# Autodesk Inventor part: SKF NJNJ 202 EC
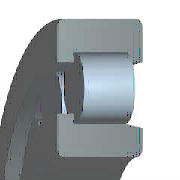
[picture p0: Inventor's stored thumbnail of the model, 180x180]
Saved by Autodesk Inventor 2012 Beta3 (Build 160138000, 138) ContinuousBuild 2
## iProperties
IsCustomPart: 0
Created: 2010-11
Part Number: SKF NJNJ 202 EC
Material: Steel, Mild
Description: Cylindrical Roller Bearings Single Row type NJ SKF
Document SubType Name: Modeling
Standard: SKF NJ
Designer: Beta-8540w
Language: en-US
Size Designation: SKF NJNJ 202 EC
Categories: <MemberInstance><Categories><Category DisplayName="Shaft Parts" InternalName="7f7aeb1f-a693-4053-b835-cee3144e0d98" Mnemonic="SHFT"><Category DisplayName="Beari
Density: 7.86 g/cm^3
Author: Beta-8540w
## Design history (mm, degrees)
node "WorkPlane1"
workplane "Work Plane2"
node "WorkPlane2"
node "Sketch1"
node "WorkPoint1"
node "Sketch3"
node "WorkPoint2"
node "WorkAxis1"
sketch "Sketch4"
  geometry: C1 r 17.5 at (0, 0) reference
hole "Hole1" sketch "Sketch4" diameter "d6" = 15 (= Diam); stored, may be unused: countersink angle "d10" = 60 deg, drill point angle "d12" = 118 deg; dims "d7" = 6, "d8" = 4, "d9" = 2, "d11" = 8
pattern_circular "PolarArray1" dims angle "d31" = 360 deg
fillet "Fillet1" dims "d32" = 0.6 (= r)
body "Solid1"
extrude "Extrusion1" new body distance "d3" = 11 (= B); taper "d4" = 0 deg
revolve "Revolution1" stored, may be unused: angle "d25" = 360 deg
revolve "Revolution2" stored, may be unused: angle "d28" = 360 deg
node "Sketch2" dims "d2" = 35 (= DD)
sketch "Sketch5"
  geometry: L1 (13.95, 1.925)-(15.15, 1.925); L2 (13.95, 0)-(13.95, 1.925); L3 (10.95, 0)-(13.95, 0); L4 (10.95, 1.925)-(10.95, 0); L5 (9.65, 1.925)-(10.95, 1.925); L6 (9.65, 9.075)-(9.65, 1.925); L7 (9.311, 11)-(9.65, 9.075); L8 (13.95, 11)-(9.311, 11); L9 (13.95, 9.075)-(13.95, 11); L10 (15.15, 9.075)-(13.95, 9.075); L11 (15.15, 1.925)-(15.15, 9.075); L12 (-17.5, 0)-(17.5, 0) reference; L13 (-17.5, 11)-(17.5, 11) reference; L14 (0, 34.914)-(0, -22.914); L15 (0, -34.479)-(0, 46.479) reference
  constraints: 24 end point, 5 collinear, 5 horizontal, 5 vertical, 1 point on line
  dimensions: "d16" = 7.15 distance of L1.end L10.start (= msp_l0); "d18" = 1.925 distance of L2.start L1.start (= 0.5 x B - 0.5 x msp_l0); "d24" = 80 deg angle of L7 L8; "d33" = 5.5 distance between parallel lines of L11 L6 (= msp_dd0); "d34" = 27.9 diameter of L9 L14 (= DD1); "d35" = 30.3 diameter of L11 L14 (= EE); "d36" = 21.9 diameter of L4 L14 (= Diam1)
sketch "Sketch6"
  geometry: L1 (12.4, 1.925)-(12.4, 9.075); L2 (15.15, 1.925)-(12.4, 1.925); L3 (15.15, 9.075)-(15.15, 1.925); L4 (12.4, 9.075)-(15.15, 9.075); L5 (-15.15, 9.075)-(15.15, 9.075) reference; L6 (-15.15, 1.925)-(15.15, 1.925) reference; L7 (12.4, 1.925)-(12.4, 9.075); L8 (15.15, 9.075)-(15.15, 1.925) reference
  constraints: 10 end point, 3 collinear, 2 horizontal, 2 vertical
  dimensions: "d27" = 2.75 distance of L1.end L5.end (= 0.5 x msp_dd0)
other parameters: "Diam" = 15 [user parameter; used in 1 equation term], "DD" = 35 [user parameter; used in 1 equation term], "B" = 11 [user parameter; used in 4 equation terms], "r" = 0.6 [user parameter; used in 1 equation term], "Fw" = 19.3 [user parameter; used in 2 equation terms], "Diam1" = 21.9 [user parameter; used in 1 equation term], "EE" = 30.3 [user parameter; used in 3 equation terms], "msp_mdtds" = 24.8 (= 0.5 x Fw + 0.5 x EE) [user parameter; used in 1 equation term], "msp_dd0" = 5.5 (= -0.5 x Fw + 0.5 x EE) [user parameter; used in 3 equation terms], "msp_l0" = 7.15 (= 0.65 x B) [user parameter; used in 2 equation terms], "DD1" = 27.9 [user parameter; used in 1 equation term], "d0" = -11 (computed from B), "d5" = 0, "d13" = 0 (derived), "d15" = 7.8 (derived), "d17" = 2.1 (derived), "d19" = 0 (derived), "d21" = 0 (derived), "d23" = 80 deg (derived), "d26" = 3.25 (derived), "d39" = 0, "d40" = 0, "d41" = 0, "d42" = 0, "d43" = 0
